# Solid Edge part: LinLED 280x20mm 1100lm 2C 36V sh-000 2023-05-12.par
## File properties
Author: jaroslaw.przewlocki
Template: iso metric part.par
Last saved by: jaroslaw.przewlocki
Revision: 1
Application: Solid Edge
Gęstość: 0,000 kg/m^3
Dokładność: 0,990
Username: jaroslaw.przewlocki
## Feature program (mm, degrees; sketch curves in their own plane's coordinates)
body "unnamed Body 1"
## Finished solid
Body 1: solid body, 1102 faces, 2854 edges, 1844 vertices.
  Faces by surface: plane 797, cylinder 149, torus 64, cone 50, spline 26, sphere 16
  Edges by curve: line 2208, curve on surface 356, circle 188, ellipse 66, spline 36
Bounding box of the edges (mm; curved faces can reach further): 279.600 x 20.000 x 4.450, from (-139.8, -10, -1) to (139.8, 10, 3.45).
Cylindrical faces by radius (mm): R0.2 x46, R0.2169 x6, R0.25 x22, R0.3373 x6, R0.4 x8, R0.4006 x2, R0.4008 x2, R0.525 x2, R0.6 x20, R1 x12, R1.1 x4, R1.1989 x2, R1.199 x2, R1.2 x10, R2.15 x5
Conical faces (half-angle, radius in mm at the cone's reference point): 0.398 deg R1.1964 x2, 0.4493 deg R1.1964 x2, 0.4746 deg R1.1948 x2, 0.4758 deg R1.1948 x2, 0.5 deg R0.5056 x4, 0.5 deg R1.0082 x4, 1 deg R0.5511 x2, 10 deg R0.2132 x4, 10 deg R0.4132 x4, 16.0099 deg R1.1053 x2, 16.1249 deg R1.1279 x2, 18.8604 deg R1.0669 x4, 19.5041 deg R0.5138 x2, 19.8244 deg R0.5099 x2, 27.363 deg R0.6214 x2, 40.6434 deg R0.5161 x2, 43.3309 deg R0.4892 x2, 45 deg R0.575 x2, 45 deg R0.625 x4
Toroidal faces (ring radius, tube radius in mm): R0.0958 r0.3997 x4, R0.1076 r0.4 x2, R0.1101 r0.4001 x2, R0.1217 r0.4 x2, R0.1234 r0.4 x2, R0.1626 r0.228 x2, R0.1634 r0.2287 x2, R0.3287 r0.2001 x2, R0.3684 r0.2151 x2, R0.3703 r0.4 x2, R0.3818 r0.2 x4, R0.4166 r0.3983 x2, R0.5981 r0.197 x2, R0.5982 r0.197 x2, R0.6009 r0.3968 x2, R0.6009 r0.3969 x2, R0.6227 r0.2 x2, R0.6235 r0.2 x2, R0.8 r0.2 x4, R0.8522 r0.3 x2, R0.9002 r0.2 x2, R0.9018 r0.2 x2, R0.9197 r0.223 x2, R0.9365 r0.2 x2, R0.9663 r0.2263 x2, R0.9665 r0.2263 x2, R1.429 r1.2 x2, R1.8741 r0.2175 x2, R1.9007 r0.2 x2
Spherical faces by radius (mm): R0.2 x12, R0.6 x4
Planar faces by outward normal: +x 93, +y 96, +z 133, -x 93, -y 97, -z 9, oblique 276
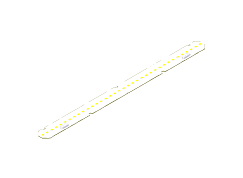
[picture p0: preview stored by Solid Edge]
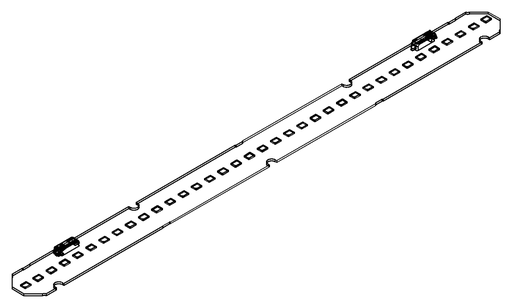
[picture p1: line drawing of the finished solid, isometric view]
